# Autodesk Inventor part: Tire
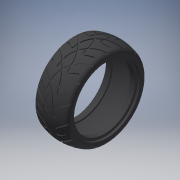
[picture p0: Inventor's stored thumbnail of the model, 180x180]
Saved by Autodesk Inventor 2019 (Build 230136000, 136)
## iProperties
Shininess: 25.0
Length Units: 11272
Angle Units: 11279
Time Units: 11290
Mass Units: 11286
Length Display Precision: 4
Angle Display Precision: 2
Compacted: True
Company: Autodesk
Created: 2000-05
Part Number: Tire
Project: Inventor Samples
User Status: IN PROGRESS
Document SubType Name: Modeling
Designer: Autodesk, Inc.
Density: 0.93 g/cm^3
Material: Rubber
Mass: 9.0169 g
Surface Area: 189.656 cm^2
Volume: 9.69559 cm^3
Appearance: Black
Density: 0.0
Volumn: 0.0
Area: 0.0
PropertySet Name: Model Information
Control State: 0
Master: False
Checked Out: False
Checked Out Date: 2018-05-30
Last Check In Date: 2018-05-30
Author: Autodesk, Inc.
Revision Number: A
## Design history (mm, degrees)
node "Revolution1" dims "d7" = 90 deg
  sketch "Sketch2"
    geometry: L1 (-10.926, 4.597)-(-14.99, 4.597); L2 (-14.99, 4.597)-(-14.99, 6.629); L3 (-14.99, 6.629)-(-16.768, 6.629); L4 (-16.768, 6.629)-(-16.768, 10.893); L5 (-19.353, -19.342)-(12.36, -19.342) reference; L6 (9.775, 10.893)-(9.775, 6.629); L7 (9.775, 6.629)-(7.997, 6.629); L8 (7.997, 6.629)-(7.997, 4.597); L9 (7.997, 4.597)-(3.933, 4.597); L10 (-10.926, 5.867)-(-13.72, 5.867); L11 (-13.72, 5.867)-(-13.72, 7.899); L12 (-13.72, 7.899)-(-15.498, 7.899); L13 (-15.498, 7.899)-(-15.498, 10.052); L14 (8.505, 10.052)-(8.505, 7.899); L15 (8.505, 7.899)-(6.727, 7.899); L16 (6.727, 7.899)-(6.727, 5.867); L17 (6.727, 5.867)-(3.933, 5.867); L18 (-10.926, 4.597)-(-10.926, 5.867); L19 (3.933, 4.597)-(3.933, 5.867); A1 r 33.02 centre (-3.496, -19.342) between (9.775, 10.893) and (-16.768, 10.893); A2 r 31.75 centre (-3.496, -19.342) between (8.505, 10.052) and (-15.498, 10.052)
    constraints: 38 end point, 9 parallel, 7 perpendicular, 4 collinear, 4 equal length, 4 point on circle, 2 centre point, 2 horizontal, 2 midpoint, 1 horizontal alignment, 9 other
    dimensions: "d0" = 47.879 diameter of L1 L5; "d1" = 51.943 diameter of L3 L5; "d2" = 1.778 distance of L2.end L3.end; "d3" = 5.842 distance from line of L4 L1.start; "d4" = 26.543 distance between parallel lines of L6 L4; "d5" = 66.04 dimension on A1 L5; "d6" = 1.27 radial gap between concentric circles of A1 A2
workaxis "Work Axis1"
node "Fillet1" dims "d8" = 3.175
sketch "Sketch7"
  geometry: L1 (-46.46, -19.342)-(23.146, -19.342) reference; A1 r 33.02 centre (-3.496, -19.342) between (7.674, 11.731) and (7.674, -50.415) reference; A2 r 32.266 centre (-3.496, -19.342) between (13.202, 8.266) and (-20.195, 8.266)
  constraints: 2 point on circle, 1 centre point, 1 coincident
feature "RevolutionSrf1" sketch "Sketch7" dims angle "d63" = 90 deg
workplane "Work Plane6"
sketch "Sketch8"
  geometry: L1 (-9.775, -14.127)-(-9.775, -13.038); L2 (-9.775, -28.085)-(-9.775, 28.085) reference; L3 (7.675, 6.132)-(7.941, 8.812); L4 (8.727, 9.228)-(13.347, 6.713); L5 (13.851, 7.638)-(9.231, 10.154); L6 (8.15, 14.674)-(8.152, 14.673); L7 (6.892, 8.916)-(6.626, 6.236); L8 (23.217, 0)-(-21.924, 0) reference; L9 (16.768, 28.085)-(16.768, -28.085) reference; A1 r 23.264 centre (-15.476, 8.428) between (-9.775, -14.127) and (7.685, 6.236); A2 r 22.21 centre (-15.476, 8.428) between (-9.775, -13.038) and (6.626, 6.236); A3 r 0.533 centre (8.472, 8.76) between (8.727, 9.228) and (7.941, 8.812); A4 r 0.527 centre (13.599, 7.175) between (13.347, 6.713) and (13.851, 7.638); A5 r 1.587 centre (8.472, 8.76) between (9.231, 10.154) and (6.892, 8.916)
  constraints: 12 end point, 11 point on circle, 6 tangent, 5 centre point, 3 parallel, 2 concentric, 1 collinear, 1 horizontal alignment
  dimensions: "d72" = 1.0541 radial gap between concentric circles of A1 A2; "d76" = 0.52705 radius of A4 (= 0.5 x d72); "d77" = 14.12735 distance from line of L1.start L8; "d78" = 1.5875 radius of A5; "d79" = 7.1755 distance from line of L8 A4.centre; "d80" = 3.16916 distance from line of L9 A4.centre
extrude "Extrusion1" cut sketch "Sketch8" stored distance "d65" = 25.4; taper "d66" = 0 deg
pattern_circular "Circular Pattern5" dims angle "d70" = 360 deg
workplane "Work Plane7"
mirror "Mirror4"
body "Solid1"
body "Srf1"
other parameters: "d64" = 18.796, "d71" = -13.2715 (= -0.5 x d4)
